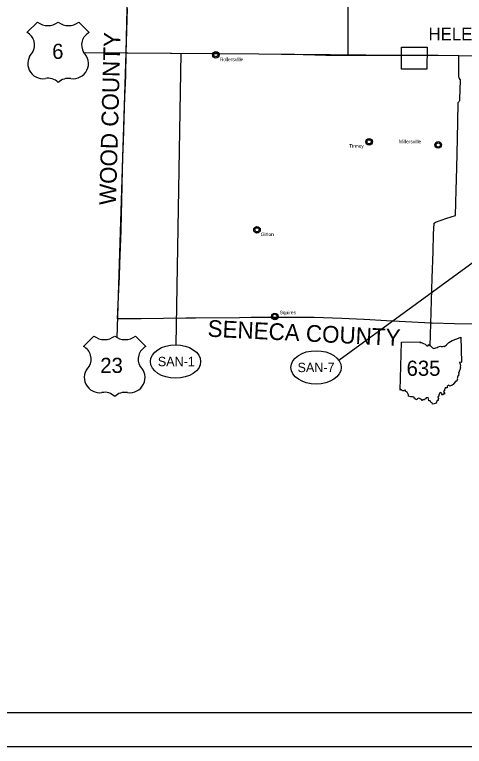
# Model space of a CAD drawing. Extents: x 0 to 798, y 0 to 440.
# Drawn here: x 132.4 to 266.6, y 0 to 218.5 of the extents above; entities that cross this region are included whole.
import ezdxf

# ---------------------------------------------------------------- set-up
doc = ezdxf.new("R2010")
doc.units = 0
for name, color, linetype in [('DV_X_Corp_Line', 7, 'Continuous'), ('GM_X_Adjacent_County_Text', 7, 'Continuous'), ('GM_X_Corporation_Text', 7, 'Continuous'), ('GM_X_County', 7, 'Continuous'), ('GM_X_State_Route', 7, 'Continuous'), ('GM_X_US_Route', 7, 'Continuous'), ('PV_P_Text', 7, 'Continuous'), ('SH_Border', 7, 'Continuous'), ('SH_Cut_Line', 7, 'Continuous'), ('SH_Data', 7, 'Continuous'), ('SH_Text', 7, 'Continuous')]:
    doc.layers.add(name, color=color, linetype=linetype)

msp = doc.modelspace()

# ---------------------------------------------------------------- linework, layer by layer
at = {"layer": 'DV_X_Corp_Line'}
msp.add_lwpolyline([(247.79, 202.22), (247.81, 208.79), (255.48, 208.81), (255.41, 202.27), (251.84, 202.23)], close=True, dxfattribs=at)
for centre, radius in [((192.44, 206.53), 0.982), ((192.44, 206.53), 0.623), ((238.18, 180.53), 0.982), ((238.18, 180.53), 0.623), ((258.79, 179.59), 0.982), ((258.79, 179.59), 0.623), ((204.72, 154.26), 0.982), ((204.72, 154.26), 0.623), ((210.02, 128.39), 0.982), ((210.02, 128.39), 0.623)]:
    msp.add_circle(centre, radius, dxfattribs=at)
at = {"layer": 'GM_X_County'}
msp.add_lwpolyline([(269.81, 126.07), (263.62, 126.19), (257.03, 126.39), (256.57, 126.41), (243.33, 127.09), (236.69, 127.45), (236.64, 127.45), (230.07, 127.79), (221.76, 128.04), (215.13, 128.1), (210.13, 128.08), (209.67, 128.08), (203.5, 128.05), (202.95, 128.04), (199.48, 128.01), (186.36, 127.86), (183.51, 127.82), (170.2, 127.66), (163.13, 127.68), (163.63, 138.59), (163.67, 139.87), (163.71, 140.9), (163.71, 141.02), (163.73, 141.65), (163.77, 142.61), (163.79, 143.45), (163.82, 144.11), (164.15, 154.06), (164.16, 154.27), (164.47, 167.36), (164.48, 167.78), (164.68, 176.47), (164.9, 180.62), (165.3, 194.01), (165.48, 197.98), (165.54, 200.35), (165.72, 207.1), (166.07, 220.3)], dxfattribs=at)
at = {"layer": 'GM_X_State_Route'}
for points in [[(162.95, 122.07), (165.72, 207.1), (168.38, 326.05)], [(231.91, 206.37), (231.94, 219.58), (232.15, 232.81), (232.29, 236.08)], [(264.54, 181.44), (264.74, 191.96), (264.74, 192.15), (264.78, 192.26), (264.86, 192.37), (264.98, 192.51), (265.06, 192.63), (265.16, 192.77), (265.2, 192.83), (265.21, 192.92), (265.23, 193.23), (265.45, 198.9), (265.43, 199.05), (265.38, 199.15), (265.06, 199.59), (264.94, 199.84), (264.9, 200.14), (264.97, 206.33)], [(256.35, 119.49), (256.99, 139.77), (257.27, 147.74), (257.42, 152.96), (257.56, 156.26), (258.02, 156.49), (261.32, 157.74), (263.98, 158.48), (264.16, 166.1), (264.33, 172.78), (264.54, 181.44)]]:
    msp.add_lwpolyline(points, dxfattribs=at)
at = {"layer": 'GM_X_US_Route'}
for points in [[(153.06, 207.19), (192.37, 206.9), (205.3, 206.83), (218.52, 206.58), (218.71, 206.58), (225.27, 206.38), (231.91, 206.37)], [(231.91, 206.37), (238.49, 206.38), (242.35, 206.38)], [(242.35, 206.38), (245.21, 206.39), (248.08, 206.42)], [(248.08, 206.42), (248.37, 206.42), (249.64, 206.42)], [(249.64, 206.42), (250.6, 206.41), (250.69, 206.41), (251.19, 206.41), (251.39, 206.41), (251.9, 206.41), (252.7, 206.4), (253.5, 206.4), (255.11, 206.4)], [(255.11, 206.4), (258.76, 206.39), (264.97, 206.33)], [(264.97, 206.33), (277.99, 206.24), (282.04, 206.26), (287.96, 206.21)]]:
    msp.add_lwpolyline(points, dxfattribs=at)
at = {"layer": 'PV_P_Text'}
for p, q in [((139.2, 216.3), (136.09, 213.19)), ((139.2, 216.3), (136.09, 213.19)), ((154.67, 213.19), (151.56, 216.3)), ((154.67, 213.19), (151.56, 216.3)), ((156.08, 122.53), (152.97, 119.42)), ((156.08, 122.53), (152.97, 119.42)), ((171.55, 119.42), (168.44, 122.53)), ((171.55, 119.42), (168.44, 122.53)), ((247.42, 106.32), (247.82, 120.68)), ((247.42, 106.32), (247.82, 120.68))]:
    msp.add_line(p, q, dxfattribs=at)
for points in [[(247.82, 120.68), (253.39, 120.77), (253.31, 120.6), (253.83, 120.56), (254.39, 120.26), (254.86, 120.06), (255.44, 119.61), (255.79, 119.61), (255.93, 119.98), (256.2, 119.7), (256.51, 119.64), (257.06, 118.96), (257.5, 118.81), (258.04, 119.04), (258.44, 119.08), (258.74, 119.32), (259.5, 119.51), (259.71, 119.39), (260.12, 119.42), (260.32, 119.51), (260.68, 119.43), (261.3, 119.95), (261.94, 120.57), (262.92, 121.15), (264.39, 121.7), (265.55, 122.19), (265.72, 114.74)], [(247.82, 120.68), (253.39, 120.77), (253.31, 120.6), (253.83, 120.56), (254.39, 120.26), (254.86, 120.06), (255.44, 119.61), (255.79, 119.61), (255.93, 119.98), (256.2, 119.7), (256.51, 119.64), (257.06, 118.96), (257.5, 118.81), (258.04, 119.04), (258.44, 119.08), (258.74, 119.32), (259.5, 119.51), (259.71, 119.39), (260.12, 119.42), (260.32, 119.51), (260.68, 119.43), (261.3, 119.95), (261.94, 120.57), (262.92, 121.15), (264.39, 121.7), (265.55, 122.19), (265.72, 114.74)], [(265.72, 114.74), (265.55, 114.63), (265.28, 114.68), (265.1, 114.47), (265.33, 114.12), (265.43, 113.76), (265.34, 113.35), (265.43, 113.01), (265.37, 112.73), (265.2, 112.45), (265.14, 112.19), (265, 111.91), (265.01, 111.75), (264.87, 111.63), (264.9, 111.16), (264.83, 110.9), (264.85, 110.68), (264.63, 110.62), (264.68, 110.44), (264.54, 110.3), (264.57, 110.05), (264.41, 109.89), (264.57, 109.58), (264.44, 109.48), (264.34, 109.1), (264.06, 109.02), (263.49, 108.33), (263.29, 108.07), (263.07, 108), (262.94, 107.73), (262.67, 107.73), (262.25, 107.54), (261.98, 107.86), (261.5, 107.48), (261.45, 107.03), (260.85, 107.04), (260.87, 106.82), (260.74, 106.75), (260.62, 106.52), (260.69, 106.12), (260.41, 106.02), (260.44, 105.78), (260.62, 105.64), (260.7, 105.19), (260.4, 105.28), (260.16, 104.91), (259.91, 105), (259.99, 105.32), (259.56, 105.7), (259.16, 105.39), (258.95, 104.9), (258.95, 104.57), (258.65, 104.37), (258.84, 103.9), (258.81, 103.58), (258.81, 103.28), (258.44, 103.29), (258.21, 102.46)], [(265.72, 114.74), (265.55, 114.63), (265.28, 114.68), (265.1, 114.47), (265.33, 114.12), (265.43, 113.76), (265.34, 113.35), (265.43, 113.01), (265.37, 112.73), (265.2, 112.45), (265.14, 112.19), (265, 111.91), (265.01, 111.75), (264.87, 111.63), (264.9, 111.16), (264.83, 110.9), (264.85, 110.68), (264.63, 110.62), (264.68, 110.44), (264.54, 110.3), (264.57, 110.05), (264.41, 109.89), (264.57, 109.58), (264.44, 109.48), (264.34, 109.1), (264.06, 109.02), (263.49, 108.33), (263.29, 108.07), (263.07, 108), (262.94, 107.73), (262.67, 107.73), (262.25, 107.54), (261.98, 107.86), (261.5, 107.48), (261.45, 107.03), (260.85, 107.04), (260.87, 106.82), (260.74, 106.75), (260.62, 106.52), (260.69, 106.12), (260.41, 106.02), (260.44, 105.78), (260.62, 105.64), (260.7, 105.19), (260.4, 105.28), (260.16, 104.91), (259.91, 105), (259.99, 105.32), (259.56, 105.7), (259.16, 105.39), (258.95, 104.9), (258.95, 104.57), (258.65, 104.37), (258.84, 103.9), (258.81, 103.58), (258.81, 103.28), (258.44, 103.29), (258.21, 102.46)], [(258.21, 102.46), (257.56, 102.3), (257.11, 102.21), (256.95, 102.58), (256.63, 102.78), (256.42, 103.16), (255.96, 103.21), (255.85, 103.73), (255.79, 104.15), (255.16, 104.04), (254.99, 103.79), (254.76, 103.72), (254.63, 103.46), (254.33, 103.44), (254, 103.32), (253.78, 103.57), (253.24, 103.83), (253, 103.96), (252.49, 103.75), (252.39, 103.51), (251.98, 103.62), (251.89, 103.89), (251.64, 103.97), (251.59, 104.25), (251.07, 104.41), (250.67, 104.35), (249.97, 104.58), (249.92, 104.95), (249.68, 105.41), (249.56, 105.73), (249.11, 105.97), (249.02, 106.35), (248.88, 106.34), (248.75, 106.19), (248.26, 106.12), (248.06, 106.27), (247.78, 106.53), (247.42, 106.32)], [(258.21, 102.46), (257.56, 102.3), (257.11, 102.21), (256.95, 102.58), (256.63, 102.78), (256.42, 103.16), (255.96, 103.21), (255.85, 103.73), (255.79, 104.15), (255.16, 104.04), (254.99, 103.79), (254.76, 103.72), (254.63, 103.46), (254.33, 103.44), (254, 103.32), (253.78, 103.57), (253.24, 103.83), (253, 103.96), (252.49, 103.75), (252.39, 103.51), (251.98, 103.62), (251.89, 103.89), (251.64, 103.97), (251.59, 104.25), (251.07, 104.41), (250.67, 104.35), (249.97, 104.58), (249.92, 104.95), (249.68, 105.41), (249.56, 105.73), (249.11, 105.97), (249.02, 106.35), (248.88, 106.34), (248.75, 106.19), (248.26, 106.12), (248.06, 106.27), (247.78, 106.53), (247.42, 106.32)]]:
    msp.add_lwpolyline(points, dxfattribs=at)
for centre, radius, start, end in [((142.29, 220.23), 5, 231.813, 308.187), ((142.29, 220.23), 5, 231.813, 308.187), ((148.47, 220.23), 5, 231.813, 308.187), ((148.47, 220.23), 5, 231.813, 308.187), ((134.15, 209.43), 4.23, 329.1175, 62.6108), ((134.15, 209.43), 4.23, 329.1175, 62.6108), ((156.62, 209.43), 4.23, 117.3892, 210.8825), ((156.62, 209.43), 4.23, 117.3892, 210.8825), ((140.89, 203.93), 4.56, 133.0046, 278.7282), ((140.89, 203.93), 4.56, 133.0046, 278.7282), ((149.88, 203.93), 4.56, 261.2718, 46.9954), ((149.88, 203.93), 4.56, 261.2718, 46.9954), ((142.42, 195.43), 4.08, 43.4177, 101.8742), ((142.42, 195.43), 4.08, 43.4177, 101.8742), ((148.43, 195.15), 4.33, 79.9613, 134.7468), ((148.43, 195.15), 4.33, 79.9613, 134.7468), ((159.17, 126.46), 5, 231.813, 308.187), ((159.17, 126.46), 5, 231.813, 308.187), ((165.35, 126.46), 5, 231.813, 308.187), ((165.35, 126.46), 5, 231.813, 308.187), ((151.02, 115.66), 4.23, 329.1175, 62.6108), ((151.02, 115.66), 4.23, 329.1175, 62.6108), ((173.5, 115.66), 4.23, 117.3892, 210.8825), ((173.5, 115.66), 4.23, 117.3892, 210.8825), ((157.76, 110.16), 4.56, 133.0046, 278.7282), ((157.76, 110.16), 4.56, 133.0046, 278.7282), ((166.76, 110.16), 4.56, 261.2718, 46.9954), ((166.76, 110.16), 4.56, 261.2718, 46.9954), ((159.3, 101.65), 4.08, 43.4177, 101.8742), ((159.3, 101.65), 4.08, 43.4177, 101.8742), ((165.31, 101.38), 4.33, 79.9613, 134.7468), ((165.31, 101.38), 4.33, 79.9613, 134.7468)]:
    msp.add_arc(centre, radius, start, end, dxfattribs=at)
at = {"layer": 'SH_Border'}
msp.add_lwpolyline([(30, 430), (670, 430), (670, 10), (30, 10)], close=True, dxfattribs=at)
at = {"layer": 'SH_Cut_Line'}
msp.add_lwpolyline([(0, 0), (680, 0), (680, 440), (0, 440)], close=True, dxfattribs=at)
at = {"layer": 'SH_Data'}
for p, q in [((180.6, 119.92), (182.06, 206.99)), ((229.11, 115.35), (290.07, 159.81))]:
    msp.add_line(p, q, dxfattribs=at)
for centre in [(180.41, 114.92), (222.36, 113.16)]:
    msp.add_ellipse(centre, major_axis=(7.5, 0), ratio=0.666667, dxfattribs=at)
at = {"layer": 'SH_Text'}
msp.add_lwpolyline([(165.72, 207.1), (205.3, 206.83), (247.8, 206.42)], dxfattribs=at)

# ---------------------------------------------------------------- texts
at = {"layer": 'DV_X_Corp_Line'}
for s, height, p in [('Rollersville', 1.0417, (193.65, 204.61)), ('Tinney', 1.042, (232.23, 178.79)), ('Millersville', 1.0417, (247.08, 180.08)), ('Girton', 1.042, (205.83, 152.38)), ('Squires', 1.042, (211.48, 129.04))]:
    msp.add_text(s, height=height, rotation=0, dxfattribs=at).set_placement(p)
at = {"layer": 'GM_X_Adjacent_County_Text'}
for s, rotation, p in [('WOOD COUNTY', 88.4388, (162.64, 161.58)), ('SENECA COUNTY', 357.1739, (189.89, 122.36))]:
    msp.add_text(s, height=5, rotation=rotation, dxfattribs=at).set_placement(p)
at = {"layer": 'GM_X_Corporation_Text'}
msp.add_text('HELENA', height=3.75, rotation=0, dxfattribs=at).set_placement((255.9, 210.84))
at = {"layer": 'PV_P_Text'}
for s, height, p in [('6', 4.53, (143.61, 205.28)), ('23', 4.528, (157.96, 111.51)), ('635', 4.528, (249.35, 110.65))]:
    msp.add_text(s, height=height, dxfattribs=at).set_placement(p)
at = {"layer": 'SH_Data'}
for s, p in [('SAN-1', (175.13, 113.52)), ('SAN-7', (216.82, 111.76))]:
    msp.add_text(s, height=2.8, dxfattribs=at).set_placement(p)

doc.saveas('drawing.dxf')
